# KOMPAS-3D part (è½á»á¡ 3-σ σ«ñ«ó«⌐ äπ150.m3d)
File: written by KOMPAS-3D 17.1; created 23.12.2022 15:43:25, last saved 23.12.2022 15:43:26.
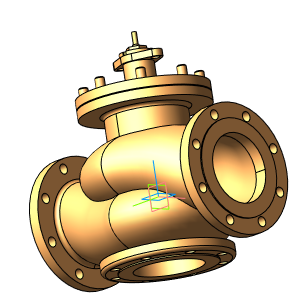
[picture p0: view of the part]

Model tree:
1. Операция без истории:2  (labels: Сталь 20  ГОСТ 1050-2013)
